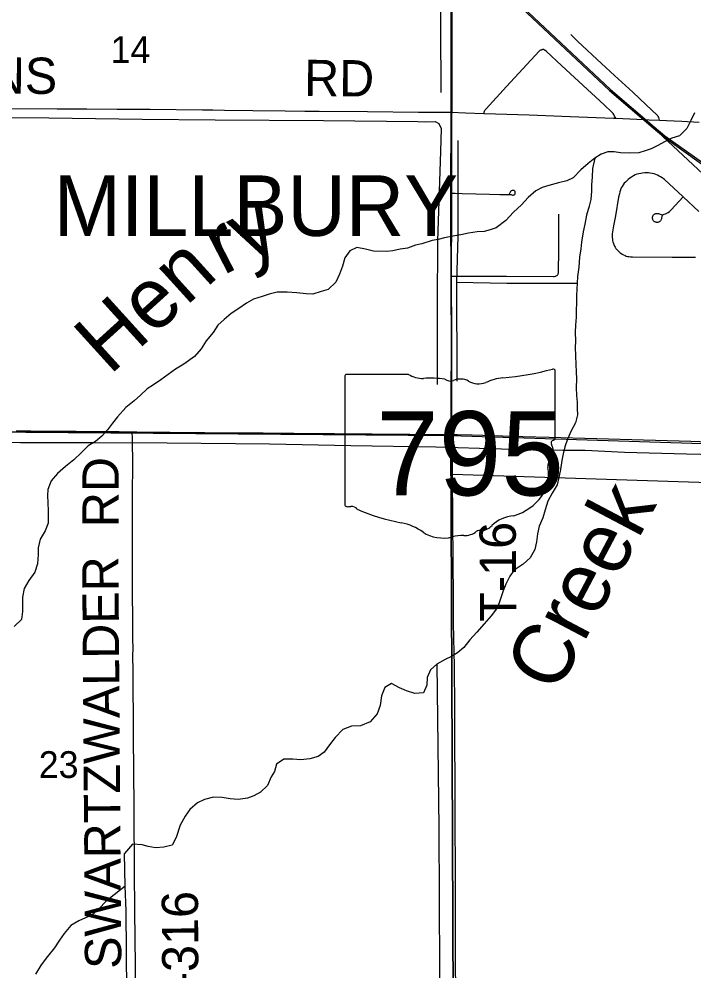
# Model space of a CAD drawing. Extents: x 0 to 34, y 0 to 22.
# Drawn here: x 3.024 to 4.081, y 16.541 to 18.031 of the extents above; entities that cross this region are included whole.
import ezdxf

# ---------------------------------------------------------------- set-up
doc = ezdxf.new("R2010")
doc.units = 0
for name, color, linetype in [('GM_X_City_Street', 7, 'Continuous'), ('GM_X_Corporation', 7, 'Continuous'), ('GM_X_Corporation_Text', 7, 'Continuous'), ('GM_X_Minor_River', 7, 'Continuous'), ('GM_X_Minor_River_Text', 7, 'Continuous'), ('GM_X_Rail_Line', 7, 'Continuous'), ('GM_X_Section', 7, 'Continuous'), ('GM_X_Section_Text', 7, 'Continuous'), ('GM_X_State_Location', 7, 'Continuous'), ('GM_X_State_Route', 7, 'Continuous'), ('GM_X_State_Shield', 7, 'Continuous'), ('GM_X_Township_Road', 7, 'Continuous'), ('GM_X_Township_Road_Text', 7, 'Continuous')]:
    doc.layers.add(name, color=color, linetype=linetype)

msp = doc.modelspace()

# ---------------------------------------------------------------- linework, layer by layer
at = {"layer": 'GM_X_City_Street'}
for points in [[(4.0272, 17.8729), (4.0265, 17.8753), (4.026, 17.8773), (4.0254, 17.8786), (4.0246, 17.8799), (4.0236, 17.8811), (4.0064, 17.8972), (3.9853, 17.9166), (3.9569, 17.9427), (3.9364, 17.9619), (3.8996, 17.9964), (3.8882, 18.007)], [(3.752, 17.8837), (3.7535, 17.887), (3.7538, 17.8879), (3.7544, 17.889), (3.7549, 17.8898), (3.7557, 17.8908), (3.7878, 17.9258), (3.8386, 17.981), (3.8405, 17.9826), (3.8413, 17.983), (3.8423, 17.9833), (3.843, 17.9835), (3.844, 17.9836)], [(3.9588, 17.876), (3.957, 17.8795), (3.9563, 17.8807), (3.9557, 17.8818), (3.9545, 17.8835), (3.9528, 17.8855), (3.9408, 17.8969), (3.8746, 17.9583), (3.8498, 17.9808), (3.8479, 17.9824), (3.8473, 17.9827), (3.8466, 17.9831), (3.8459, 17.9834), (3.845, 17.9836), (3.844, 17.9836)], [(3.7013, 17.8853), (3.7236, 17.8847), (3.752, 17.8837), (3.7703, 17.883), (3.823, 17.8813), (3.8872, 17.8789), (3.9551, 17.8762), (3.9588, 17.876), (3.9917, 17.8745), (4.011, 17.8736), (4.0272, 17.8729), (4.0384, 17.8724), (4.062, 17.8713), (4.0893, 17.87)], [(4.0888, 17.7299), (4.0645, 17.7528), (4.0637, 17.7535), (4.035, 17.7801), (4.033, 17.7816), (4.0312, 17.7829), (4.0289, 17.7843), (4.0265, 17.7856), (4.024, 17.7869), (4.0216, 17.7879), (4.0188, 17.7888), (4.0159, 17.7896), (4.0129, 17.7901), (4.01, 17.7904), (4.007, 17.7906), (4.0041, 17.7905), (4.0006, 17.7901), (3.9979, 17.7898), (3.9949, 17.7891), (3.992, 17.7883), (3.9893, 17.7872), (3.9864, 17.7858), (3.9832, 17.784), (3.9808, 17.7822), (3.978, 17.7799), (3.9759, 17.7782), (3.9738, 17.7762), (3.9721, 17.7743), (3.9703, 17.7719), (3.9687, 17.7693), (3.9674, 17.7669), (3.9661, 17.7641), (3.9652, 17.7611), (3.9644, 17.7578), (3.963, 17.7523), (3.9583, 17.7234), (3.9555, 17.7075), (3.9534, 17.6951), (3.9532, 17.6923), (3.9533, 17.6895), (3.9535, 17.6868), (3.9538, 17.6846), (3.9544, 17.6824), (3.9551, 17.6802), (3.9558, 17.6782), (3.9569, 17.6759), (3.958, 17.6742), (3.9591, 17.6723), (3.9607, 17.6704), (3.962, 17.6689), (3.9634, 17.6675), (3.965, 17.6661), (3.9668, 17.6649), (3.9689, 17.6634), (3.9711, 17.6621), (3.9733, 17.6612), (3.9753, 17.6604), (3.9772, 17.6599), (3.9793, 17.6596), (3.9817, 17.6593), (3.9849, 17.6592), (4.047, 17.6587), (4.0834, 17.6586)], [(3.7012, 17.7587), (3.7071, 17.7586), (3.7183, 17.7584), (3.7613, 17.7573), (3.777, 17.7569), (3.7909, 17.7569), (3.7923, 17.7569), (3.7939, 17.7567), (3.795, 17.7565), (3.7961, 17.756), (3.797, 17.7558), (3.798, 17.7557), (3.7991, 17.7559), (3.7999, 17.7563), (3.8006, 17.7569), (3.8011, 17.7577), (3.8013, 17.7584), (3.8015, 17.7594), (3.8014, 17.7602), (3.8011, 17.7612), (3.8006, 17.7621), (3.7997, 17.7628), (3.7991, 17.763), (3.7981, 17.7632), (3.7972, 17.7632), (3.7964, 17.763), (3.7955, 17.7626), (3.795, 17.7623), (3.7945, 17.7618), (3.7941, 17.7613), (3.7921, 17.7574)], [(4.0312, 17.7244), (4.0305, 17.7195), (4.0302, 17.7184), (4.0298, 17.7173), (4.0294, 17.7164), (4.0289, 17.7156), (4.0284, 17.7151), (4.0279, 17.7146), (4.0272, 17.7141), (4.0265, 17.7137), (4.0255, 17.7133), (4.0246, 17.7131), (4.0236, 17.713), (4.0227, 17.7131), (4.0218, 17.7132), (4.0209, 17.7134), (4.0201, 17.7138), (4.0195, 17.7141), (4.0188, 17.7146), (4.0183, 17.715), (4.0178, 17.7155), (4.0174, 17.7161), (4.017, 17.7168), (4.0168, 17.7174), (4.0166, 17.718), (4.0164, 17.719), (4.0163, 17.7199), (4.0163, 17.7208), (4.0164, 17.7216), (4.0167, 17.7224), (4.017, 17.7232), (4.0174, 17.7239), (4.0178, 17.7246), (4.0185, 17.7252), (4.0192, 17.7258), (4.0199, 17.7262), (4.0207, 17.7265), (4.0216, 17.7268), (4.0225, 17.7271), (4.0235, 17.7271), (4.0243, 17.7271), (4.0251, 17.7271), (4.0259, 17.7269), (4.0301, 17.7253), (4.0309, 17.7251), (4.0315, 17.725), (4.0323, 17.7251), (4.0334, 17.7254), (4.0348, 17.7258), (4.0368, 17.7265), (4.0387, 17.7275), (4.0407, 17.7286), (4.0428, 17.73), (4.0456, 17.7326), (4.0645, 17.7528)], [(3.8673, 17.6305), (3.868, 17.6314), (3.8684, 17.6321), (3.8687, 17.6329), (3.8689, 17.6339), (3.8691, 17.635), (3.8694, 17.6703), (3.8694, 17.7011), (3.8698, 17.7261)], [(3.7012, 17.6289), (3.7226, 17.6287), (3.7878, 17.6288), (3.8613, 17.6283), (3.8629, 17.6284), (3.8642, 17.6287), (3.8654, 17.6292), (3.8664, 17.6298), (3.8673, 17.6305)]]:
    msp.add_lwpolyline(points, dxfattribs=at)
at = {"layer": 'GM_X_Corporation'}
msp.add_lwpolyline([(4.7035, 17.0079), (4.4431, 17.0144), (4.4423, 17.294), (4.2034, 17.3023), (4.2031, 17.1122), (4.1368, 17.1138), (4.1367, 17.3044), (3.7029, 17.3184), (3.7023, 17.3641), (3.7022, 17.3816), (3.7013, 17.6306), (3.7003, 17.7209), (3.7005, 17.7576), (3.7011, 17.8859), (3.7017, 18.3895)], dxfattribs=at)
at = {"layer": 'GM_X_Minor_River'}
for points in [[(3.6822, 19.3289), (3.6819, 19.1889), (3.681, 19.0371), (3.6798, 18.8869), (3.6814, 18.6793), (3.6829, 18.4869), (3.6822, 18.3674), (3.6836, 18.1207), (3.6849, 17.9161)], [(2.7148, 17.8797), (2.8766, 17.8775), (3.0711, 17.8766), (3.2171, 17.8747), (3.3317, 17.8736), (3.5011, 17.8724), (3.6487, 17.8711), (3.6611, 17.8705), (3.6759, 17.8707), (3.6815, 17.8676), (3.6856, 17.8599), (3.6842, 17.8242), (3.6798, 17.6839), (3.6789, 17.583), (3.6793, 17.4592)], [(4.082, 17.8846), (4.0765, 17.8726), (4.0703, 17.8598), (4.0588, 17.8486), (4.0466, 17.8446), (4.0363, 17.8398), (4.0237, 17.8328), (4.0142, 17.8284), (4.0047, 17.8251), (3.9948, 17.8219), (3.98, 17.8214), (3.9664, 17.822), (3.9562, 17.8233)], [(3.7117, 17.8413), (3.7113, 17.6917), (3.7094, 17.6197), (3.71, 17.4644)], [(3.9562, 17.8233), (3.9464, 17.8234), (3.9357, 17.8198), (3.9258, 17.8135), (3.9155, 17.8053), (3.904, 17.7953), (3.892, 17.7826), (3.8821, 17.7782), (3.8692, 17.775), (3.854, 17.771), (3.8434, 17.7674), (3.8335, 17.7623), (3.8216, 17.7522), (3.8112, 17.7406), (3.7989, 17.729), (3.7866, 17.7159), (3.7716, 17.7044), (3.7621, 17.7015), (3.7526, 17.699), (3.742, 17.6984), (3.728, 17.696), (3.7162, 17.6936), (3.7068, 17.6918), (3.6904, 17.689), (3.6809, 17.6865), (3.6711, 17.6848), (3.6551, 17.6794), (3.6452, 17.6772), (3.6327, 17.6729), (3.6213, 17.6712), (3.6095, 17.6687), (3.5997, 17.6677), (3.5797, 17.6681), (3.5668, 17.6713), (3.5536, 17.6738), (3.5426, 17.6683), (3.5345, 17.6578), (3.5309, 17.6445), (3.5261, 17.6321), (3.5203, 17.6197), (3.5087, 17.6081), (3.4977, 17.6049), (3.4844, 17.6009), (3.4738, 17.6011), (3.4595, 17.6028), (3.4443, 17.6038), (3.4285, 17.6037), (3.4163, 17.6005), (3.4049, 17.5969), (3.3916, 17.5929), (3.3805, 17.5866), (3.3687, 17.5781), (3.3568, 17.5703), (3.3457, 17.561), (3.3357, 17.5521), (3.3284, 17.5408), (3.3176, 17.5277), (3.3098, 17.5153), (3.299, 17.5029), (3.2826, 17.4911), (3.2692, 17.4833), (3.2581, 17.4751), (3.2462, 17.4666), (3.2351, 17.4588), (3.2248, 17.4525), (3.2148, 17.4428), (3.2045, 17.4339), (3.1915, 17.4231), (3.1787, 17.4089), (3.171, 17.3987), (3.1629, 17.3882), (3.1541, 17.3785), (3.1441, 17.3699), (3.1326, 17.3633), (3.1223, 17.3528), (3.1104, 17.3413), (3.0973, 17.3312), (3.0847, 17.32), (3.0747, 17.3084), (3.0695, 17.2952), (3.069, 17.2858), (3.0696, 17.274), (3.0701, 17.2615), (3.0698, 17.2421), (3.0651, 17.2304), (3.0573, 17.2173), (3.0545, 17.2036), (3.0543, 17.1934), (3.0533, 17.1786), (3.0493, 17.1658), (3.0397, 17.1523), (3.0323, 17.1402), (3.0298, 17.1262), (3.0296, 17.1137), (3.0298, 17.1038), (3.0285, 17.0913), (3.017, 17.0805)], [(3.9258, 17.8135), (3.9222, 17.7973), (3.9216, 17.784), (3.921, 17.7718), (3.9208, 17.762), (3.9195, 17.7487), (3.9171, 17.7385), (3.9131, 17.7245), (3.9102, 17.7102), (3.9077, 17.6984), (3.9052, 17.6822), (3.9039, 17.6715), (3.9022, 17.6587), (3.9008, 17.6431), (3.8991, 17.6284), (3.8985, 17.6181), (3.8976, 17.6083), (3.8971, 17.598), (3.8966, 17.5646), (3.896, 17.5521), (3.8954, 17.5411), (3.896, 17.5271), (3.8954, 17.5172), (3.8956, 17.5047), (3.8962, 17.4899), (3.8967, 17.4796), (3.8973, 17.4678), (3.8967, 17.4546), (3.8973, 17.442), (3.8983, 17.4314), (3.8985, 17.4215), (3.8991, 17.412), (3.8959, 17.3992), (3.8892, 17.3868), (3.8834, 17.3736), (3.879, 17.3619), (3.8766, 17.3509), (3.8745, 17.3403), (3.8724, 17.3263), (3.87, 17.3161), (3.8671, 17.3025), (3.859, 17.2893), (3.8523, 17.2765), (3.848, 17.2633), (3.8444, 17.2505), (3.8389, 17.2377), (3.836, 17.2256), (3.8347, 17.2131), (3.8319, 17.201), (3.8248, 17.1882), (3.8137, 17.1781), (3.7999, 17.1688), (3.793, 17.1591), (3.7864, 17.147), (3.7824, 17.1361), (3.778, 17.1225), (3.7737, 17.1101), (3.7636, 17.0973), (3.7529, 17.0846), (3.7413, 17.0719), (3.7305, 17.0595), (3.7209, 17.0475), (3.7109, 17.0393), (3.7014, 17.0338), (3.6918, 17.029), (3.6785, 17.0216), (3.6689, 17.0127), (3.6634, 17.0006), (3.6628, 16.9885), (3.6577, 16.9768), (3.6441, 16.9759), (3.6309, 16.9799), (3.62, 16.9843), (3.6076, 16.9913), (3.5973, 16.985), (3.5918, 16.9722), (3.5897, 16.957), (3.5853, 16.9438), (3.5742, 16.9315), (3.5593, 16.9249), (3.5449, 16.9248), (3.5316, 16.9193), (3.5193, 16.9066), (3.5104, 16.8953), (3.5023, 16.8837), (3.4927, 16.877), (3.4798, 16.8734), (3.4658, 16.8718), (3.4529, 16.8731), (3.4389, 16.873), (3.4275, 16.8652), (3.4243, 16.8535), (3.4192, 16.8452), (3.4137, 16.8316), (3.4026, 16.8212), (3.3919, 16.8153), (3.382, 16.812), (3.3676, 16.81), (3.3551, 16.8106), (3.3423, 16.8127), (3.3291, 16.8132)], [(3.7094, 17.6197), (3.7882, 17.6179), (3.8985, 17.6181)], [(4.1803, 17.3479), (4.0695, 17.3504), (3.9727, 17.3528), (3.9107, 17.356), (3.8759, 17.3562), (3.7798, 17.3582), (3.677, 17.3613), (3.5442, 17.3635), (3.4168, 17.3659), (3.2564, 17.3674), (3.1429, 17.3681), (3.0268, 17.368), (2.8123, 17.3688)], [(3.6785, 17.0216), (3.6816, 16.7654), (3.6827, 16.5423), (3.6841, 16.3464), (3.6825, 16.1017), (3.6821, 15.8805), (3.6804, 15.6582), (3.6808, 15.4396), (3.6814, 15.3334), (3.6828, 15.1345), (3.683, 15.0055), (3.6833, 14.8112), (3.6833, 14.6667)], [(3.3291, 16.8132), (3.315, 16.8097), (3.3039, 16.8045), (3.2917, 16.7941), (3.2843, 16.7836), (3.2769, 16.7697), (3.2706, 16.7501), (3.2643, 16.7384), (3.2514, 16.7352), (3.2381, 16.7339), (3.2268, 16.736), (3.217, 16.7388), (3.2023, 16.7398), (3.1894, 16.725)], [(3.1937, 14.6594), (3.1937, 14.9), (3.1943, 15.1508), (3.1942, 15.339), (3.1938, 15.6247), (3.1921, 15.8008), (3.1928, 16.0148), (3.1938, 16.2242), (3.194, 16.3798), (3.1923, 16.6356), (3.1907, 16.6743), (3.1894, 16.725)], [(3.1907, 16.6743), (3.1734, 16.6606), (3.1616, 16.6513), (3.1489, 16.6382), (3.1385, 16.6285), (3.1286, 16.6245), (3.1183, 16.6201), (3.1057, 16.6123), (3.0949, 16.6), (3.0876, 16.5898), (3.0802, 16.5778), (3.069, 16.5643), (3.059, 16.5508), (3.0504, 16.5365)]]:
    msp.add_lwpolyline(points, dxfattribs=at)
at = {"layer": 'GM_X_Rail_Line'}
for points in [[(2.1, 19.6439), (2.1012, 19.6428), (2.4982, 19.2743), (2.9696, 18.8359), (3.3468, 18.4857), (3.702, 18.1547), (3.9505, 17.921), (4.0191, 17.8627), (4.0357, 17.8486), (4.0945, 17.8067), (4.1695, 17.7587), (4.2566, 17.7148), (4.3444, 17.681), (4.4559, 17.6499), (4.5498, 17.6344), (4.6383, 17.6263), (4.7029, 17.6237), (4.7039, 17.6237)], [(2.1, 19.64), (2.4967, 19.2714), (2.9674, 18.8343), (3.3458, 18.483), (3.6997, 18.1544), (3.9489, 17.9193), (4.0176, 17.861), (4.0342, 17.8468), (4.0931, 17.8048), (4.1683, 17.7567), (4.2556, 17.7127), (4.3436, 17.6788), (4.4554, 17.6477), (4.5495, 17.6321), (4.6381, 17.624), (4.7029, 17.6214), (4.7039, 17.6214)], [(4.0173, 17.8615), (4.3536, 17.5482), (4.5597, 17.354), (4.6999, 17.2234)]]:
    msp.add_lwpolyline(points, dxfattribs=at)
at = {"layer": 'GM_X_Section'}
for points in [[(2.6966, 18.4009), (3.7032, 18.3885), (3.7003, 17.3796), (2.7017, 17.3873)], [(3.7003, 17.3796), (3.7046, 16.3661), (2.7079, 16.3715), (2.7017, 17.3873)], [(4.6959, 16.4195), (4.6953, 16.3562), (3.7046, 16.3661), (3.7003, 17.3796), (4.7018, 17.3475)]]:
    msp.add_lwpolyline(points, close=True, dxfattribs=at)
at = {"layer": 'GM_X_State_Route'}
msp.add_line((3.6995, 17.381), (3.7025, 17.381), dxfattribs=at)
for points in [[(3.02, 17.3869), (3.043, 17.3866), (3.071, 17.3863), (3.1139, 17.3861), (3.1332, 17.3859), (3.181, 17.3856), (3.2018, 17.3854), (3.209, 17.3853), (3.2606, 17.3847), (3.3153, 17.3843), (3.4067, 17.3836), (3.4546, 17.3831), (3.5186, 17.3827), (3.6361, 17.3817), (3.6759, 17.3812), (3.6995, 17.381)], [(3.7025, 17.381), (3.711, 17.3809), (3.7342, 17.3804), (3.7505, 17.38)], [(3.7505, 17.38), (3.7659, 17.3796), (3.8134, 17.3781), (3.8544, 17.377), (3.9292, 17.375), (3.9839, 17.3734), (4.0765, 17.3708), (4.1045, 17.3698), (4.1492, 17.369), (4.1799, 17.3681), (4.1924, 17.3678), (4.2034, 17.3675), (4.2153, 17.3669), (4.2552, 17.3652), (4.2904, 17.3638), (4.3285, 17.3621), (4.3494, 17.3616), (4.3678, 17.3608), (4.4164, 17.3587), (4.4415, 17.3575)]]:
    msp.add_lwpolyline(points, dxfattribs=at)
at = {"layer": 'GM_X_State_Shield'}
for p, q in [((3.864, 17.3754), (3.864, 17.4801)), ((3.5344, 17.4717), (3.5344, 17.2716)), ((3.6342, 17.4752), (3.5377, 17.4752)), ((3.864, 17.3755), (3.864, 17.3754))]:
    msp.add_line(p, q, dxfattribs=at)
for centre, major_axis, start_param, end_param in [((3.7466, 17.748), (0.3495, 0), 4.814394, 5.042369), ((3.8603, 17.4806), (0.00367, 0), 6.141152, 7.989035), ((3.5382, 17.4721), (0.00382, 0), 1.712693, 3.28349), ((3.6572, 17.4984), (0.037, 0), 4.042523, 4.731795), ((3.6694, 17.3628), (0.133, 0), 1.404758, 1.657858), ((3.6996, 17.4732), (0.0107, 0), 3.836095, 5.185415), ((3.7153, 17.4501), (0.0222, 0), 0.950623, 2.079405), ((3.744, 17.4818), (0.0267, 0), 4.081561, 5.145723), ((3.7912, 17.414), (0.0703, 0), 1.699011, 2.107814), ((3.8601, 17.375), (0.00393, 0), 5.05454, 6.418171), ((3.8631, 17.3678), (0.00568, 0), 1.883978, 3.671073), ((3.827, 17.3545), (0.0341, 0), 5.934695, 6.695948), ((3.8771, 17.3316), (0.0248, 0), 2.387724, 3.262537), ((3.7662, 17.3183), (0.0874, 0), 5.101752, 6.440018), ((3.5382, 17.2712), (0.00385, 0), 3.00124, 4.508301), ((3.5388, 17.2916), (0.0294, 0), 4.665946, 4.897461), ((3.5448, 17.2601), (0.0106, 0), 0.519207, 1.627899), ((3.6786, 17.4399), (0.2524, 0), 4.195997, 4.488961), ((3.803, 17.2154), (0.0479, 0), 1.647645, 2.488434), ((3.6034, 17.1817), (0.079, 0), 0.823519, 1.323587), ((3.7424, 17.2522), (0.0282, 0), 4.937069, 5.64225), ((3.6888, 17.2591), (0.0501, 0), 4.026481, 4.996735), ((3.7214, 17.2441), (0.0267, 0), 4.691044, 5.507374), ((3.7456, 17.2247), (0.00752, 0), 1.147584, 2.315152), ((3.7178, 17.1899), (0.0412, 0), 1.495662, 1.94098)]:
    msp.add_ellipse(centre, major_axis=major_axis, ratio=0.8, start_param=start_param, end_param=end_param, dxfattribs=at)
at = {"layer": 'GM_X_Township_Road'}
for points in [[(3.7013, 17.8853), (3.7013, 17.9049), (3.7013, 17.9142), (3.7016, 17.9626), (3.7017, 18.0186), (3.702, 18.0589), (3.7016, 18.1427), (3.702, 18.1526), (3.7019, 18.2004), (3.7018, 18.3079), (3.7022, 18.3893)], [(2.699, 17.8939), (2.7078, 17.8938), (2.8247, 17.8928), (2.8869, 17.8924), (2.9366, 17.892), (2.9944, 17.8913), (3.084, 17.891), (3.1306, 17.8907), (3.1779, 17.8902), (3.2295, 17.89), (3.3115, 17.8891), (3.3277, 17.889), (3.3462, 17.8887), (3.3904, 17.8883), (3.4413, 17.8877), (3.4718, 17.8873), (3.4942, 17.8873), (3.57, 17.8867), (3.6499, 17.8856), (3.6726, 17.8854), (3.6869, 17.8853), (3.6944, 17.8853), (3.7013, 17.8853)], [(3.7012, 17.7587), (3.7013, 17.7962), (3.7013, 17.854), (3.7013, 17.8853)], [(3.7012, 17.6289), (3.7014, 17.6501), (3.7013, 17.7171), (3.7012, 17.7587)], [(3.7025, 17.381), (3.7023, 17.4039), (3.7022, 17.4574), (3.7022, 17.4928), (3.7019, 17.5537), (3.7014, 17.6091), (3.7012, 17.6289)], [(3.2071, 16.4651), (3.2068, 16.5473), (3.2061, 16.595), (3.2059, 16.6329), (3.2052, 16.7007), (3.2051, 16.7305), (3.2048, 16.7573), (3.2046, 16.7753), (3.2045, 16.7983), (3.2037, 16.9084), (3.2036, 16.9357), (3.2032, 16.9873), (3.2031, 16.9992), (3.2031, 17.0103), (3.2028, 17.0358), (3.203, 17.0458), (3.2028, 17.062), (3.2021, 17.1633), (3.2023, 17.2187), (3.2021, 17.2895), (3.2025, 17.3325), (3.2019, 17.3747), (3.2018, 17.3854)], [(3.7031, 17.3184), (3.7026, 17.3635), (3.7025, 17.381)], [(3.7078, 16.3671), (3.7078, 16.3913), (3.708, 16.4435), (3.7083, 16.4877), (3.7081, 16.5778), (3.7078, 16.6593), (3.7076, 16.7091), (3.7074, 16.7644), (3.7071, 16.8378), (3.707, 16.8988), (3.707, 16.9516), (3.7063, 17.0194), (3.7057, 17.0399), (3.7048, 17.0859), (3.7046, 17.1244), (3.7037, 17.2457), (3.7031, 17.3184)]]:
    msp.add_lwpolyline(points, dxfattribs=at)

# ---------------------------------------------------------------- texts
at = {"layer": 'GM_X_Corporation_Text'}
msp.add_text('MILLBURY', height=0.0947, rotation=0, dxfattribs=at).set_placement((3.0786, 17.6919))
at = {"layer": 'GM_X_Minor_River_Text'}
for s, height, rotation, p in [('ry', 0.09476, 27.2025, (3.3436, 17.6293)), ('Hen', 0.09476, 42.2059, (3.1663, 17.4726)), ('Creek', 0.09477, 62.2045, (3.8659, 16.973))]:
    msp.add_text(s, height=height, rotation=rotation, dxfattribs=at).set_placement(p)
at = {"layer": 'GM_X_Section_Text'}
for s, p in [('14', (3.1678, 17.9626)), ('23', (3.0553, 16.8435))]:
    msp.add_text(s, height=0.04186, rotation=0, dxfattribs=at).set_placement(p)
at = {"layer": 'GM_X_State_Location'}
for s in ['s', 'r']:
    msp.add_text(s, height=0.000189, dxfattribs=at).set_placement((3.6955, 17.3584))
msp.add_text('795', height=0.000189, rotation=0, dxfattribs=at).set_placement((3.6286, 17.3446))
at = {"layer": 'GM_X_State_Shield'}
msp.add_text('795', height=0.13184, dxfattribs=at).set_placement((3.5835, 17.2857))
at = {"layer": 'GM_X_Township_Road_Text'}
for s, height, rotation, p in [('COLLINS', 0.05682, 359.6752, (2.7589, 17.9158)), ('RD', 0.05682, 359.5114, (3.4706, 17.9108)), ('RD', 0.05682, 90, (3.1805, 17.236)), ('T-16', 0.05682, 90.3535, (3.8031, 17.0882)), ('SWARTZWALDER', 0.056818, 90.4073, (3.1846, 16.5448)), ('T-316', 0.05682, 90.2805, (3.3056, 16.4682))]:
    msp.add_text(s, height=height, rotation=rotation, dxfattribs=at).set_placement(p)

doc.saveas('drawing.dxf')
